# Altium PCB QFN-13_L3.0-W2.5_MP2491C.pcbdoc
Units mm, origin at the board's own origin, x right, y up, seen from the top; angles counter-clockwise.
Board outline 15.94 x 16.31 mm, 2 copper layers (Top Layer, Bottom Layer), stack 0 mm thick; 1 components, 0 nets, 13 pads, 0 vias.
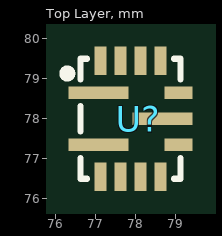
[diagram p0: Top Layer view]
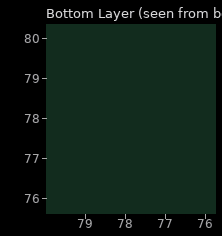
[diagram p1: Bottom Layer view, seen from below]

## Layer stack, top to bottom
Top Layer: signal copper (thickness not stored)
Bottom Layer: signal copper (thickness not stored)

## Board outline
85.786,69.85 69.85,69.85 69.85,86.161 85.786,86.161

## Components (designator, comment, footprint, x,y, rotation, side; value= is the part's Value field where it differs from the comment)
U? "" QFN-13_L3.0-W2.5_MP2491C 78.08,78.006 r0 top

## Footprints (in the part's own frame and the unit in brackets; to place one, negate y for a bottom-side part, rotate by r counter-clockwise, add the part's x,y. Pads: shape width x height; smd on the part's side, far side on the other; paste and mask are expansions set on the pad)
QFN-13_L3.0-W2.5_MP2491C [mil]
  rect 59x12 smd paste+0 mask+1.97: 1(-39.39,25.6) 2(-39.39,-25.6) 8(23.69,0)
  rect 12x28 smd paste+0 mask+1.97: 3(-37.38,-57.09) 4(-17.69,-57.09) 5(1.99,-57.09) 6(21.68,-57.09) 10(21.68,57.09) 11(1.99,57.09) 12(-17.69,57.09) 13(-37.38,57.09)
  rect 28x12 smd paste+0 mask+1.97: 7(39.39,-25.6) 9(39.39,25.6)
  silkscreen extent -74,-59 41,59

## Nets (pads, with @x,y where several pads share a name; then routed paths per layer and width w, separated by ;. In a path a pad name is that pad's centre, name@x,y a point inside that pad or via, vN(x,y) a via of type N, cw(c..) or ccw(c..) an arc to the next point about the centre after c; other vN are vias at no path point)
pads on no net: U?.1 U?.2 U?.3 U?.4 U?.5 U?.6 U?.7 U?.8 U?.9 U?.10 U?.11 U?.12 U?.13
